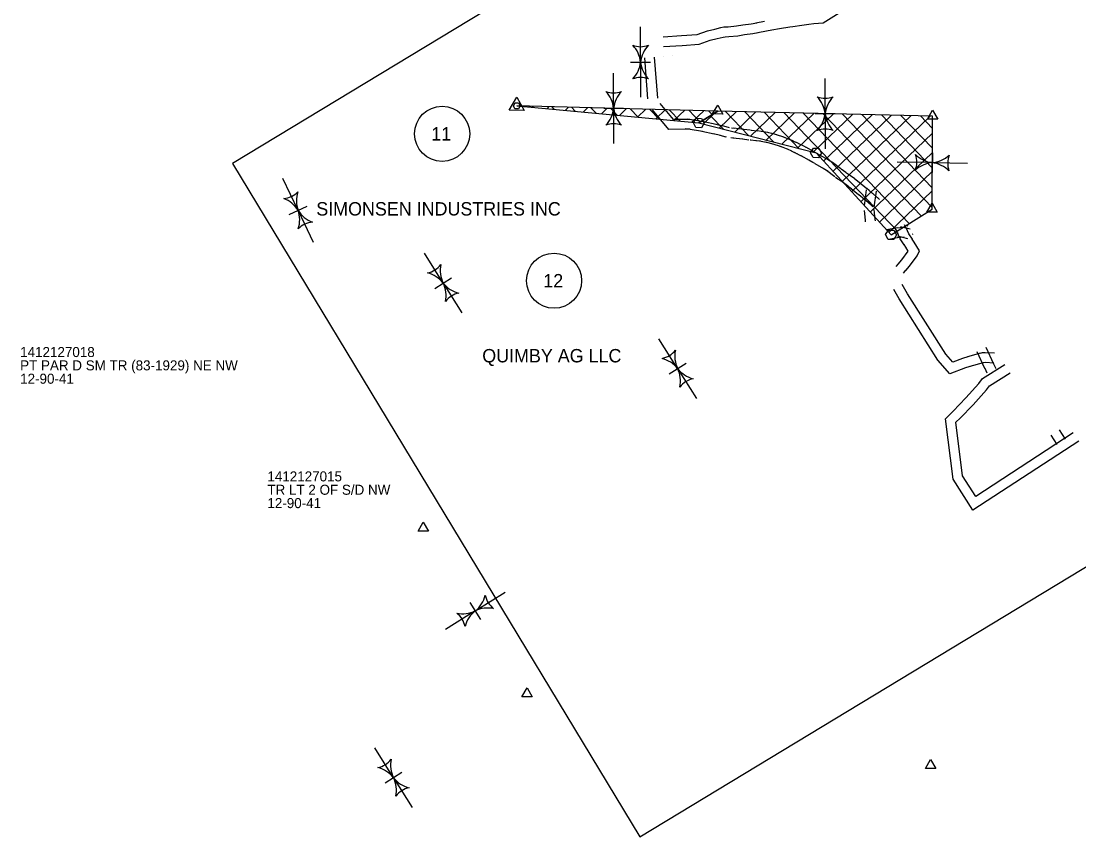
# Model space of a CAD drawing. Extents: x 14265071 to 14303042, y 8620873 to 8637932.
# Drawn here: x 14284442 to 14284979, y 8637266 to 8637681 of the extents above; entities that cross this region are included whole.
import ezdxf

# ---------------------------------------------------------------- set-up
doc = ezdxf.new("R2010")
doc.units = 0
for name, color, linetype in [('_CIVIL_CONSTRUCTION', 7, 'Continuous'), ('Alignment', 7, 'Continuous'), ('Profile', 7, 'Continuous'), ('SurTerrainImportedContoursMajor', 7, 'Continuous'), ('TextAlignment', 7, 'Continuous'), ('TextAlignmentLrg', 7, 'Continuous'), ('TextAlignmentSml', 7, 'Continuous')]:
    doc.layers.add(name, color=color, linetype=linetype)

msp = doc.modelspace()

# ---------------------------------------------------------------- linework, layer by layer
at = {"layer": '_CIVIL_CONSTRUCTION'}
for p, q in [((14284815.09, 8637679.69), (14284819.44, 8637680.59)), ((14284816.1, 8637674.79), (14284820.45, 8637675.69)), ((14284820.61, 8637675.72), (14284823.22, 8637676.17)), ((14284767.91, 8637672.68), (14284777.3, 8637673.3)), ((14284768.24, 8637667.7), (14284777.62, 8637668.31)), ((14284760.26, 8637641.15), (14284758.6, 8637661.91)), ((14284765.25, 8637641.55), (14284763.59, 8637662.31)), ((14284767.98, 8637662.53), (14284767.98, 8637662.53)), ((14284772.97, 8637662.93), (14284772.97, 8637662.93)), ((14284760.26, 8637641.14), (14284760.26, 8637641.15)), ((14284765.25, 8637641.54), (14284765.25, 8637641.55)), ((14284771.63, 8637634.9), (14284771.63, 8637634.9)), ((14284776.61, 8637635.3), (14284776.61, 8637635.3)), ((14284781.22, 8637630.67), (14284780.54, 8637630.81)), ((14284788.89, 8637629.39), (14284781.46, 8637630.62)), ((14284795, 8637628.12), (14284788.69, 8637629.43)), ((14284798.31, 8637627.32), (14284794.84, 8637628.16)), ((14284801.25, 8637626.53), (14284798.2, 8637627.34)), ((14284801.64, 8637626.42), (14284801.17, 8637626.55)), ((14284780.16, 8637625.78), (14284779.48, 8637625.93)), ((14284788.07, 8637624.46), (14284780.64, 8637625.69)), ((14284793.99, 8637623.22), (14284787.67, 8637624.53)), ((14284797.13, 8637622.46), (14284793.66, 8637623.3)), ((14284799.96, 8637621.7), (14284796.91, 8637622.51)), ((14284800.27, 8637621.61), (14284799.8, 8637621.75)), ((14284803.91, 8637621.14), (14284802.33, 8637621.25)), ((14284804.25, 8637626.13), (14284802.67, 8637626.24)), ((14284808.47, 8637620.59), (14284803.41, 8637621.19)), ((14284809.06, 8637625.56), (14284804, 8637626.16)), ((14284812.18, 8637625.13), (14284808.98, 8637625.57)), ((14284812.84, 8637625.08), (14284812.57, 8637625.09)), ((14284815.98, 8637624.78), (14284812.66, 8637625.09)), ((14284818.07, 8637624.5), (14284815.79, 8637624.8)), ((14284821.27, 8637623.94), (14284817.89, 8637624.52)), ((14284821.71, 8637623.86), (14284821.15, 8637623.97)), ((14284823.04, 8637623.56), (14284821.6, 8637623.88)), ((14284825.74, 8637622.77), (14284822.74, 8637623.64)), ((14284829.3, 8637621.59), (14284825.55, 8637622.83)), ((14284830.21, 8637621.25), (14284829.13, 8637621.65)), ((14284833.34, 8637619.99), (14284830.08, 8637621.3)), ((14284811.51, 8637620.18), (14284808.3, 8637620.61)), ((14284815.51, 8637619.8), (14284812.19, 8637620.11)), ((14284812.56, 8637620.09), (14284812.28, 8637620.1)), ((14284817.42, 8637619.54), (14284815.14, 8637619.84)), ((14284820.43, 8637619.02), (14284817.04, 8637619.6)), ((14284820.73, 8637618.95), (14284820.17, 8637619.06)), ((14284821.97, 8637618.68), (14284820.53, 8637618.99)), ((14284824.36, 8637617.97), (14284821.36, 8637618.83)), ((14284827.73, 8637616.85), (14284823.98, 8637618.09)), ((14284828.47, 8637616.56), (14284827.4, 8637616.96)), ((14284831.48, 8637615.35), (14284828.21, 8637616.67)), ((14284835.5, 8637619.02), (14284833.17, 8637620.06)), ((14284837.08, 8637618.26), (14284835.39, 8637619.07)), ((14284838.55, 8637617.54), (14284837.02, 8637618.29)), ((14284839.56, 8637617.02), (14284838.48, 8637617.57)), ((14284840.64, 8637616.46), (14284839.56, 8637617.02)), ((14284844.75, 8637614.21), (14284840.52, 8637616.53)), ((14284833.46, 8637614.45), (14284831.13, 8637615.5)), ((14284834.92, 8637613.75), (14284833.24, 8637614.56)), ((14284836.33, 8637613.05), (14284834.81, 8637613.81)), ((14284837.28, 8637612.57), (14284836.2, 8637613.12)), ((14284838.36, 8637612.01), (14284837.28, 8637612.57)), ((14284842.35, 8637609.82), (14284838.12, 8637612.14)), ((14284846.55, 8637613.16), (14284844.64, 8637614.27)), ((14284847.65, 8637612.5), (14284846.5, 8637613.2)), ((14284852.15, 8637609.89), (14284847.71, 8637612.47)), ((14284844.04, 8637608.84), (14284842.13, 8637609.95)), ((14284845.08, 8637608.21), (14284843.93, 8637608.91)), ((14284849.64, 8637605.57), (14284845.2, 8637608.14)), ((14284851.93, 8637604.15), (14284849.4, 8637605.71)), ((14284854.56, 8637608.4), (14284852.03, 8637609.96)), ((14284858.26, 8637605.49), (14284854.13, 8637608.7)), ((14284859.67, 8637604.51), (14284858.5, 8637605.31)), ((14284855.19, 8637601.54), (14284851.06, 8637604.75)), ((14284856.85, 8637600.38), (14284855.68, 8637601.18)), ((14284858.02, 8637599.59), (14284856.85, 8637600.38)), ((14284858.19, 8637599.47), (14284857.91, 8637599.66)), ((14284860.84, 8637603.71), (14284859.67, 8637604.51)), ((14284861.06, 8637603.56), (14284860.79, 8637603.75)), ((14284861.34, 8637603.37), (14284861.06, 8637603.56)), ((14284863.31, 8637601.91), (14284861.24, 8637603.43)), ((14284865.37, 8637600.39), (14284863.31, 8637601.91)), ((14284866.03, 8637599.87), (14284865.26, 8637600.47)), ((14284866.8, 8637599.27), (14284866.03, 8637599.87)), ((14284858.46, 8637599.28), (14284858.19, 8637599.47)), ((14284860.34, 8637597.89), (14284858.28, 8637599.41)), ((14284862.41, 8637596.36), (14284860.34, 8637597.89)), ((14284862.96, 8637595.93), (14284862.19, 8637596.53)), ((14284863.73, 8637595.33), (14284862.96, 8637595.93)), ((14284865.49, 8637593.91), (14284863.61, 8637595.42)), ((14284868.62, 8637597.81), (14284866.75, 8637599.32)), ((14284870.5, 8637596.3), (14284868.62, 8637597.81)), ((14284870.39, 8637586.67), (14284871.45, 8637594.9)), ((14284871.57, 8637595.46), (14284870.56, 8637596.25)), ((14284872.64, 8637594.59), (14284871.5, 8637595.52)), ((14284874.48, 8637593.06), (14284872.58, 8637594.65)), ((14284867.36, 8637592.4), (14284865.49, 8637593.91)), ((14284868.5, 8637591.52), (14284867.48, 8637592.31)), ((14284869.5, 8637590.71), (14284868.36, 8637591.63)), ((14284871.27, 8637589.22), (14284869.37, 8637590.81)), ((14284873.69, 8637587.09), (14284871.08, 8637589.39)), ((14284877, 8637590.84), (14284874.38, 8637593.14)), ((14284875.34, 8637586.02), (14284876.41, 8637594.25)), ((14284877.99, 8637589.93), (14284876.92, 8637590.91)), ((14284870.84, 8637579.38), (14284870.35, 8637584.42)), ((14284874.6, 8637586.24), (14284873.54, 8637587.23)), ((14284875.81, 8637579.86), (14284875.33, 8637584.9)), ((14284870.91, 8637578.57), (14284870.83, 8637579.42)), ((14284875.89, 8637579.04), (14284875.81, 8637579.88)), ((14284886.91, 8637575.53), (14284881.77, 8637574.59)), ((14284886.31, 8637575.45), (14284886.01, 8637575.45)), ((14284889.97, 8637575.79), (14284886.81, 8637575.47)), ((14284887.55, 8637572.86), (14284887.39, 8637573.03)), ((14284893.64, 8637574.83), (14284888.58, 8637576.12)), ((14284891.28, 8637576.18), (14284891.13, 8637576.35)), ((14284892.38, 8637576.67), (14284892.05, 8637576.47)), ((14284887.81, 8637570.61), (14284882.67, 8637569.67)), ((14284886.31, 8637570.45), (14284886, 8637570.45)), ((14284890.47, 8637570.81), (14284887.31, 8637570.5)), ((14284892.4, 8637569.98), (14284887.35, 8637571.27)), ((14284894.95, 8637572.38), (14284894.62, 8637572.18)), ((14284936.13, 8637506.24), (14284932.19, 8637514.72)), ((14284929.36, 8637511.78), (14284922.64, 8637509.92)), ((14284931.59, 8637504.13), (14284927.66, 8637512.61)), ((14284930.7, 8637506.97), (14284923.98, 8637505.1)), ((14284932.73, 8637501.75), (14284931.64, 8637504.03)), ((14284937.24, 8637503.91), (14284936.15, 8637506.19)), ((14284972.51, 8637468.12), (14284969.54, 8637472.85)), ((14284968.28, 8637465.46), (14284965.31, 8637470.19))]:
    msp.add_line(p, q, dxfattribs=at)
for points in [[(14284823.16, 8637676.16), (14284827.18, 8637676.91), (14284832.36, 8637677.76), (14284833.89, 8637677.98), (14284838.51, 8637678.65), (14284841.98, 8637679.13), (14284844.61, 8637679.4), (14284847.04, 8637679.6), (14284849.4, 8637679.7), (14284862.87, 8637688.27), (14284872.42, 8637698.06)], [(14284777.26, 8637673.3), (14284785.29, 8637673.86), (14284790.55, 8637675.71), (14284794.33, 8637676.61), (14284797.29, 8637677.35), (14284798.82, 8637677.71), (14284801.03, 8637677.76), (14284805.22, 8637678.19), (14284808.49, 8637678.79), (14284812.8, 8637679.33), (14284815.54, 8637679.77)], [(14284777.61, 8637668.32), (14284786.31, 8637668.92), (14284791.96, 8637670.91), (14284795.52, 8637671.75), (14284798.46, 8637672.49), (14284799.45, 8637672.72), (14284801.34, 8637672.77), (14284805.93, 8637673.23), (14284809.26, 8637673.85), (14284813.51, 8637674.38), (14284816.33, 8637674.83)], [(14284781.62, 8637630.7), (14284779.18, 8637630.69), (14284773.22, 8637630.63), (14284766.41, 8637638.72)], [(14284781.64, 8637625.7), (14284779.22, 8637625.69), (14284770.91, 8637625.6), (14284762.58, 8637635.5)], [(14284890.53, 8637566.95), (14284888.45, 8637570.04), (14284887.01, 8637573.35), (14284886.3, 8637574.61)], [(14284894.68, 8637569.73), (14284892.85, 8637572.46), (14284891.49, 8637575.58), (14284890.66, 8637577.06)], [(14284891.3, 8637553.87), (14284893.19, 8637556.12), (14284897.1, 8637561.37), (14284898.32, 8637563.85), (14284895.6, 8637568.32), (14284894.64, 8637569.78)], [(14284887.47, 8637557.08), (14284889.26, 8637559.22), (14284892.58, 8637563.67), (14284891.37, 8637565.65), (14284890.46, 8637567.04)], [(14284886.37, 8637555.84), (14284887.63, 8637557.27)], [(14284890.12, 8637552.53), (14284891.38, 8637553.97)], [(14284922.91, 8637510), (14284920.11, 8637509.06), (14284915.19, 8637507.27), (14284911.67, 8637511.27), (14284892.24, 8637542), (14284889.53, 8637546.74)], [(14284924.51, 8637505.27), (14284921.76, 8637504.34), (14284913.68, 8637501.4), (14284907.65, 8637508.27), (14284887.95, 8637539.42), (14284885.19, 8637544.26)], [(14284936.45, 8637511.83), (14284931.74, 8637512.09), (14284930.09, 8637511.94), (14284929.11, 8637511.72)], [(14284979.24, 8637467.13), (14284925.36, 8637431.99), (14284915.43, 8637447.81), (14284911.49, 8637478.49), (14284915.38, 8637482.38), (14284921.9, 8637489.06), (14284928.46, 8637496.45), (14284930.42, 8637498.95), (14284941.75, 8637506.06)], [(14284936.18, 8637506.84), (14284931.83, 8637507.08), (14284930.86, 8637506.99), (14284930.19, 8637506.84)], [(14284976.51, 8637471.32), (14284926.89, 8637438.96), (14284920.25, 8637449.54), (14284916.76, 8637476.69), (14284918.94, 8637478.86), (14284925.56, 8637485.66), (14284932.3, 8637493.24), (14284933.82, 8637495.17), (14284944.41, 8637501.83)]]:
    msp.add_lwpolyline(points, dxfattribs=at)
at = {"layer": 'Alignment'}
for centre in [(14284655.62, 8637623.35), (14284712.53, 8637548.68)]:
    msp.add_circle(centre, 14.01, dxfattribs=at)
at = {"layer": 'Profile'}
for p, q in [((14284693.57, 8637637.59), (14284786.09, 8637628.87)), ((14284786.09, 8637628.87), (14284845.7, 8637613.62)), ((14284845.7, 8637613.62), (14284883.86, 8637572.04))]:
    msp.add_line(p, q, dxfattribs=at)
at = {"layer": 'SurTerrainImportedContoursMajor'}
for p, q in [((14284699.75, 8637637), (14284700.18, 8637637.41)), ((14284701.43, 8637637.38), (14284701.99, 8637636.79)), ((14284708.96, 8637636.14), (14284710.03, 8637637.16)), ((14284711.38, 8637637.13), (14284712.66, 8637635.79)), ((14284718.17, 8637635.27), (14284719.87, 8637636.91)), ((14284721.32, 8637636.87), (14284723.33, 8637634.78)), ((14284727.37, 8637634.4), (14284729.72, 8637636.65)), ((14284731.27, 8637636.61), (14284733.99, 8637633.78)), ((14284736.58, 8637633.53), (14284739.56, 8637636.4)), ((14284741.22, 8637636.35), (14284744.66, 8637632.77)), ((14284745.79, 8637632.67), (14284749.41, 8637636.14)), ((14284751.17, 8637636.1), (14284755.32, 8637631.77)), ((14284754.99, 8637631.8), (14284759.25, 8637635.89)), ((14284761.12, 8637635.84), (14284765.99, 8637630.76)), ((14284764.2, 8637630.93), (14284769.1, 8637635.63)), ((14284771.06, 8637635.58), (14284776.65, 8637629.76)), ((14284773.4, 8637630.06), (14284778.94, 8637635.38)), ((14284781.01, 8637635.33), (14284786.79, 8637629.31)), ((14284782.61, 8637629.2), (14284788.79, 8637635.12)), ((14284788.4, 8637628.28), (14284794.5, 8637634.14)), ((14284790.96, 8637635.07), (14284792.85, 8637633.1)), ((14284791.99, 8637632.57), (14284798.62, 8637625.66)), ((14284796.38, 8637626.24), (14284805.21, 8637634.71)), ((14284799.5, 8637634.85), (14284811.47, 8637622.38)), ((14284804.36, 8637624.2), (14284815.08, 8637634.47)), ((14284809.43, 8637634.61), (14284824.33, 8637619.09)), ((14284812.35, 8637622.15), (14284824.94, 8637634.24)), ((14284819.37, 8637634.37), (14284837.18, 8637615.8)), ((14284820.33, 8637620.11), (14284834.8, 8637634)), ((14284828.31, 8637618.07), (14284844.66, 8637633.76)), ((14284829.3, 8637634.13), (14284886.99, 8637574)), ((14284836.29, 8637616.03), (14284854.52, 8637633.52)), ((14284839.23, 8637633.89), (14284893.05, 8637577.8)), ((14284844.28, 8637613.99), (14284864.38, 8637633.28)), ((14284849.17, 8637633.65), (14284899.11, 8637581.6)), ((14284849.59, 8637609.39), (14284874.24, 8637633.04)), ((14284854.33, 8637604.23), (14284884.1, 8637632.8)), ((14284859.06, 8637599.07), (14284893.96, 8637632.56)), ((14284859.1, 8637633.41), (14284904.68, 8637585.9)), ((14284863.79, 8637593.91), (14284903.82, 8637632.32)), ((14284869.03, 8637633.17), (14284904.74, 8637595.95)), ((14284878.96, 8637632.92), (14284904.79, 8637606)), ((14284888.9, 8637632.68), (14284904.85, 8637616.05)), ((14284898.83, 8637632.44), (14284904.91, 8637626.11)), ((14284868.53, 8637588.75), (14284904.89, 8637623.65)), ((14284873.26, 8637583.59), (14284904.84, 8637613.89)), ((14284877.99, 8637578.43), (14284904.78, 8637604.14)), ((14284882.73, 8637573.27), (14284904.73, 8637594.38))]:
    msp.add_line(p, q, dxfattribs=at)
at = {"layer": 'TextAlignment'}
msp.add_lwpolyline([(14284549.13, 8637608.21), (14284756.21, 8637265.98), (14285292.07, 8637590.22), (14285084.99, 8637932.44)], close=True, dxfattribs=at)
at = {"layer": 'TextAlignmentLrg'}
for p, q in [((14284693.57, 8637637.59), (14284786.09, 8637628.87)), ((14284795.79, 8637634.94), (14284693.57, 8637637.59)), ((14284786.09, 8637628.87), (14284795.79, 8637634.94)), ((14284795.79, 8637634.94), (14284786.09, 8637628.87)), ((14284904.94, 8637632.29), (14284795.79, 8637634.94)), ((14284904.68, 8637585.09), (14284904.94, 8637632.29)), ((14284786.09, 8637628.87), (14284845.7, 8637613.62)), ((14284845.7, 8637613.62), (14284883.86, 8637572.04)), ((14284883.86, 8637572.04), (14284904.68, 8637585.09))]:
    msp.add_line(p, q, dxfattribs=at)
at = {"layer": 'TextAlignmentSml'}
for p, q in [((14284756.52, 8637659.8), (14284756.52, 8637677.69)), ((14284751.46, 8637659.8), (14284761.58, 8637659.8)), ((14284756.52, 8637659.8), (14284756.52, 8637641.92)), ((14284742.82, 8637636.31), (14284742.82, 8637654.2)), ((14284850.37, 8637633.62), (14284850.37, 8637651.51)), ((14284689.65, 8637635.43), (14284693.66, 8637642.06)), ((14284691.82, 8637637.62), (14284692.73, 8637639.12)), ((14284692.66, 8637636.09), (14284691.82, 8637637.62)), ((14284692.73, 8637639.12), (14284694.48, 8637639.08)), ((14284693.66, 8637642.06), (14284697.4, 8637635.27)), ((14284695.32, 8637637.55), (14284694.41, 8637636.05)), ((14284694.48, 8637639.08), (14284695.32, 8637637.55)), ((14284793.13, 8637633.48), (14284795.85, 8637637.97)), ((14284795.85, 8637637.97), (14284798.38, 8637633.37)), ((14284697.4, 8637635.27), (14284689.65, 8637635.43)), ((14284694.41, 8637636.05), (14284692.66, 8637636.09)), ((14284737.76, 8637636.31), (14284747.88, 8637636.31)), ((14284742.82, 8637636.31), (14284742.82, 8637618.43)), ((14284798.38, 8637633.37), (14284793.13, 8637633.48)), ((14284845.3, 8637633.62), (14284855.43, 8637633.62)), ((14284850.37, 8637633.62), (14284850.37, 8637615.73)), ((14284902.32, 8637630.78), (14284904.94, 8637635.32)), ((14284904.94, 8637635.32), (14284907.57, 8637630.78)), ((14284783.34, 8637628.92), (14284784.76, 8637631.28)), ((14284784.66, 8637626.52), (14284783.34, 8637628.92)), ((14284784.76, 8637631.28), (14284787.51, 8637631.22)), ((14284788.84, 8637628.81), (14284787.41, 8637626.46)), ((14284787.51, 8637631.22), (14284788.84, 8637628.81)), ((14284907.57, 8637630.78), (14284902.32, 8637630.78)), ((14284787.41, 8637626.46), (14284784.66, 8637626.52)), ((14284842.95, 8637613.68), (14284844.38, 8637616.03)), ((14284844.38, 8637616.03), (14284847.13, 8637615.98)), ((14284847.13, 8637615.98), (14284848.45, 8637613.57)), ((14284844.28, 8637611.27), (14284842.95, 8637613.68)), ((14284847.03, 8637611.22), (14284844.28, 8637611.27)), ((14284848.45, 8637613.57), (14284847.03, 8637611.22)), ((14284904.9, 8637613.75), (14284904.72, 8637603.63)), ((14284904.81, 8637608.69), (14284886.93, 8637609.01)), ((14284904.81, 8637608.69), (14284922.69, 8637608.37)), ((14284582.38, 8637584.45), (14284574.67, 8637600.59)), ((14284577.82, 8637582.27), (14284586.95, 8637586.63)), ((14284582.38, 8637584.45), (14284590.1, 8637568.31)), ((14284902.05, 8637583.57), (14284904.68, 8637588.12)), ((14284907.3, 8637583.57), (14284902.05, 8637583.57)), ((14284904.68, 8637588.12), (14284907.3, 8637583.57)), ((14284881.11, 8637572.09), (14284882.53, 8637574.45)), ((14284882.53, 8637574.45), (14284885.28, 8637574.39)), ((14284885.28, 8637574.39), (14284886.61, 8637571.98)), ((14284882.44, 8637569.68), (14284881.11, 8637572.09)), ((14284885.18, 8637569.63), (14284882.44, 8637569.68)), ((14284886.61, 8637571.98), (14284885.18, 8637569.63)), ((14284656.14, 8637547.49), (14284646.65, 8637562.65)), ((14284651.85, 8637544.8), (14284660.43, 8637550.18)), ((14284656.14, 8637547.49), (14284665.63, 8637532.33)), ((14284775.36, 8637504.01), (14284765.86, 8637519.16)), ((14284771.07, 8637501.32), (14284779.65, 8637506.7)), ((14284775.36, 8637504.01), (14284784.86, 8637488.85)), ((14284643.41, 8637421.41), (14284646.04, 8637425.96)), ((14284646.04, 8637425.96), (14284648.66, 8637421.41)), ((14284648.66, 8637421.41), (14284643.41, 8637421.41)), ((14284672.44, 8637380.82), (14284687.6, 8637390.32)), ((14284669.75, 8637385.11), (14284675.13, 8637376.53)), ((14284672.44, 8637380.82), (14284657.29, 8637371.32)), ((14284696.22, 8637337.19), (14284698.85, 8637341.74)), ((14284698.85, 8637341.74), (14284701.47, 8637337.19)), ((14284701.47, 8637337.19), (14284696.22, 8637337.19)), ((14284630.91, 8637296.03), (14284621.4, 8637311.17)), ((14284901.29, 8637300.69), (14284903.92, 8637305.23)), ((14284903.92, 8637305.23), (14284906.54, 8637300.69)), ((14284635.2, 8637298.72), (14284626.63, 8637293.33)), ((14284906.54, 8637300.69), (14284901.29, 8637300.69)), ((14284630.91, 8637296.03), (14284640.43, 8637280.88))]:
    msp.add_line(p, q, dxfattribs=at)
for centre, radius, start, end in [((14284742.02, 8637658.25), 14.59, 6.1059, 43.9131), ((14284756.52, 8637679), 11.35, 249.3932, 290.6068), ((14284771.03, 8637658.25), 14.59, 136.0869, 173.8941), ((14284742.02, 8637661.35), 14.59, 316.0869, 353.8941), ((14284771.03, 8637661.35), 14.59, 186.1059, 223.9131), ((14284756.52, 8637640.61), 11.35, 69.3932, 110.6068), ((14284728.32, 8637634.76), 14.59, 6.1059, 43.9131), ((14284742.82, 8637655.51), 11.35, 249.3932, 290.6068), ((14284757.33, 8637634.76), 14.59, 136.0869, 173.8941), ((14284835.86, 8637632.07), 14.59, 6.1059, 43.9131), ((14284850.37, 8637652.81), 11.35, 249.3932, 290.6068), ((14284864.87, 8637632.07), 14.59, 136.0869, 173.8941), ((14284728.32, 8637637.86), 14.59, 316.0869, 353.8941), ((14284757.33, 8637637.86), 14.59, 186.1059, 223.9131), ((14284835.86, 8637635.17), 14.59, 316.0869, 353.8941), ((14284864.87, 8637635.17), 14.59, 186.1059, 223.9131), ((14284742.82, 8637617.12), 11.35, 69.3932, 110.6068), ((14284850.37, 8637614.43), 11.35, 69.3932, 110.6068), ((14284885.62, 8637609.03), 11.35, 338.3683, 19.5819), ((14284906.62, 8637623.17), 14.59, 225.062, 262.8692), ((14284903.52, 8637623.22), 14.59, 275.0809, 312.8882), ((14284924, 8637608.35), 11.35, 158.3683, 199.5819), ((14284906.1, 8637594.16), 14.59, 95.0809, 132.8882), ((14284903, 8637594.22), 14.59, 45.062, 82.8692), ((14284574.11, 8637601.77), 11.35, 274.9368, 316.1504), ((14284569.97, 8637576.8), 14.59, 31.6494, 69.4567), ((14284596.14, 8637589.3), 14.59, 161.6305, 199.4377), ((14284594.8, 8637592.1), 14.59, 211.6494, 249.4567), ((14284568.63, 8637579.6), 14.59, 341.6305, 19.4377), ((14284590.66, 8637567.13), 11.35, 94.9368, 136.1504), ((14284645.95, 8637563.76), 11.35, 281.4494, 322.663), ((14284669.26, 8637553.87), 14.59, 168.1431, 205.9503), ((14284644.67, 8637538.48), 14.59, 38.162, 75.9693), ((14284667.61, 8637556.5), 14.59, 218.162, 255.9693), ((14284643.02, 8637541.11), 14.59, 348.1431, 25.9503), ((14284666.33, 8637531.22), 11.35, 101.4494, 142.663), ((14284765.16, 8637520.27), 11.35, 281.4796, 322.6933), ((14284763.89, 8637494.99), 14.59, 38.1923, 75.9995), ((14284788.47, 8637510.4), 14.59, 168.1733, 205.9806), ((14284786.82, 8637513.03), 14.59, 218.1923, 255.9995), ((14284762.24, 8637497.62), 14.59, 348.1733, 25.9806), ((14284785.55, 8637487.75), 11.35, 101.4796, 142.6933), ((14284663.42, 8637392.28), 14.59, 308.1923, 345.9995), ((14284688.7, 8637391.01), 11.35, 191.4796, 232.6933), ((14284666.05, 8637393.93), 14.59, 258.1733, 295.9806), ((14284656.18, 8637370.62), 11.35, 11.4796, 52.6933), ((14284681.46, 8637369.35), 14.59, 128.1923, 165.9995), ((14284678.83, 8637367.7), 14.59, 78.1733, 115.9806), ((14284620.7, 8637312.28), 11.35, 281.5323, 322.7459), ((14284644.02, 8637302.43), 14.59, 168.226, 206.0333), ((14284619.46, 8637287), 14.59, 38.245, 76.0522), ((14284617.81, 8637289.62), 14.59, 348.226, 26.0333), ((14284642.37, 8637305.06), 14.59, 218.245, 256.0522), ((14284641.12, 8637279.77), 11.35, 101.5323, 142.7459)]:
    msp.add_arc(centre, radius, start, end, dxfattribs=at)

# ---------------------------------------------------------------- texts
at = {"layer": '_CIVIL_CONSTRUCTION'}
for s, p in [('1412127018', (14284441.08, 8637509.88)), ('PT PAR D SM TR (83-1929) NE NW', (14284441.08, 8637503.1)), ('12-90-41', (14284441.08, 8637496.32)), ('1412127015', (14284566.78, 8637446.66)), ('TR LT 2 OF S/D NW', (14284566.78, 8637439.87)), ('12-90-41', (14284566.78, 8637433.09))]:
    msp.add_text(s, height=5.1, dxfattribs=at).set_placement(p)
at = {"layer": 'Alignment'}
for s, p in [('11', (14284650.12, 8637619.95)), ('SIMONSEN INDUSTRIES INC', (14284591.65, 8637581.82)), ('12', (14284707.06, 8637545.28)), ('QUIMBY AG LLC', (14284676.02, 8637507.16))]:
    msp.add_text(s, height=6.8, dxfattribs=at).set_placement(p)

doc.saveas('drawing.dxf')
